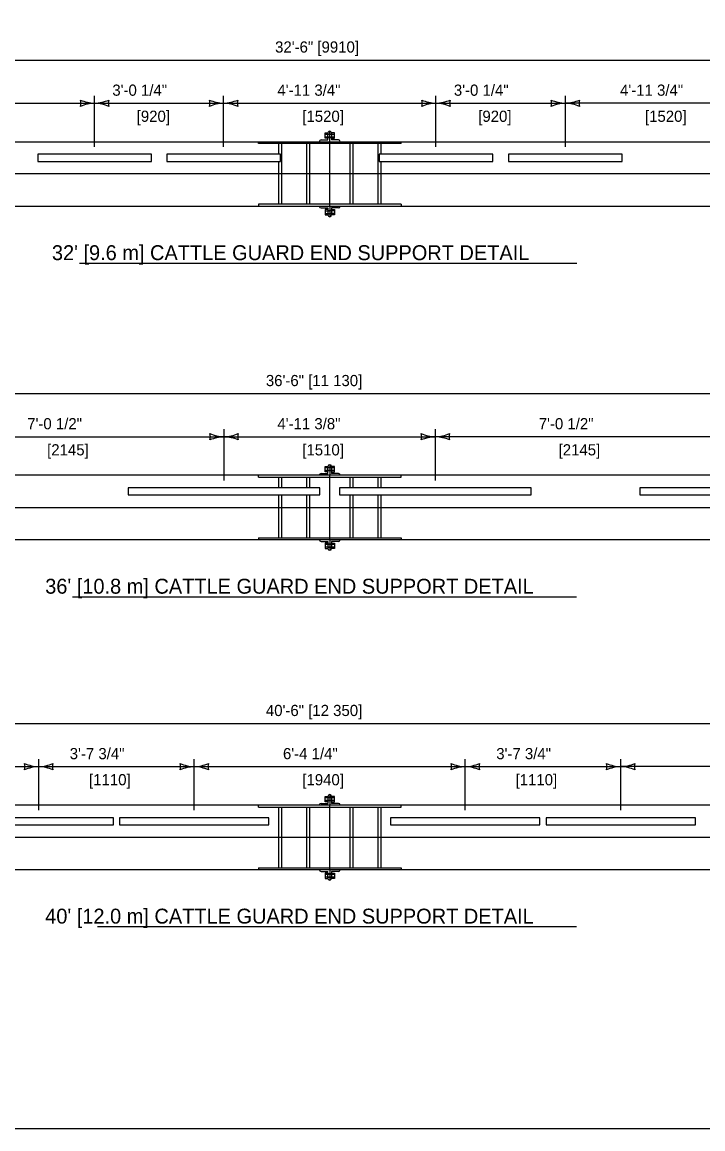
# Model space of a CAD drawing. Extents: x 49991.4 to 50021, y 49987.6 to 50011.4.
# Drawn here: x 50003.05 to 50006.69, y 49987.8 to 49993.74 of the extents above; entities that cross this region are included whole.
import ezdxf

# ---------------------------------------------------------------- set-up
doc = ezdxf.new("R2010")
doc.units = 0
for name, color, linetype in [('Level 1', 7, 'Continuous'), ('Level 2', 7, 'Continuous'), ('Level 3', 7, 'Continuous'), ('Level 4', 7, 'Continuous'), ('Level 5', 7, 'Continuous')]:
    doc.layers.add(name, color=color, linetype=linetype)

msp = doc.modelspace()

# ---------------------------------------------------------------- linework, layer by layer
at = {"layer": 'Level 1'}
for p, q in [((50004.669, 49993.1125), (50004.669, 49993.141)), ((50004.669, 49993.141), (50004.684, 49993.141)), ((50004.669, 49993.1339), (50004.7185, 49993.1339)), ((50004.684, 49993.1035), (50004.684, 49993.141)), ((50004.6937, 49993.0937), (50004.6937, 49993.1508)), ((50004.7185, 49993.141), (50004.7035, 49993.141)), ((50004.7035, 49993.141), (50004.7035, 49993.1035)), ((50004.7185, 49993.1125), (50004.7185, 49993.141)), ((50000.9788, 49993.0937), (50008.4087, 49993.0937)), ((50004.3112, 49993.084), (50004.3112, 49993.0937)), ((50005.0762, 49993.084), (50004.3112, 49993.084)), ((50004.4195, 49993.084), (50004.4195, 49993.0265)), ((50004.4355, 49993.084), (50004.4355, 49992.7585)), ((50004.5695, 49993.084), (50004.5695, 49992.7585)), ((50004.5855, 49993.084), (50004.5855, 49992.7585)), ((50004.6472, 49993.1035), (50004.684, 49993.1035)), ((50004.669, 49993.1196), (50004.7185, 49993.1196)), ((50004.684, 49993.1125), (50004.669, 49993.1125)), ((50004.6937, 49992.7487), (50004.6937, 49993.0937)), ((50004.7035, 49993.1125), (50004.7185, 49993.1125)), ((50004.7402, 49993.1035), (50004.7035, 49993.1035)), ((50004.802, 49993.084), (50004.802, 49992.7585)), ((50004.818, 49993.084), (50004.818, 49992.7585)), ((50004.952, 49993.084), (50004.952, 49992.7585)), ((50004.968, 49993.084), (50004.968, 49993.0265)), ((50005.0762, 49993.084), (50005.0762, 49993.0937)), ((50003.7383, 49993.0265), (50003.1287, 49993.0265)), ((50003.1287, 49993.0265), (50003.1287, 49992.9884)), ((50003.7383, 49992.9884), (50003.7383, 49993.0265)), ((50004.4295, 49993.0265), (50003.8199, 49993.0265)), ((50003.8199, 49993.0265), (50003.8199, 49992.9884)), ((50004.4295, 49992.9884), (50004.4295, 49993.0265)), ((50005.5676, 49993.0265), (50004.958, 49993.0265)), ((50004.958, 49993.0265), (50004.958, 49992.9884)), ((50005.5676, 49992.9884), (50005.5676, 49993.0265)), ((50006.2614, 49993.0265), (50005.6518, 49993.0265)), ((50005.6518, 49993.0265), (50005.6518, 49992.9884)), ((50006.2614, 49992.9884), (50006.2614, 49993.0265)), ((50003.1287, 49992.9884), (50003.7383, 49992.9884)), ((50003.8199, 49992.9884), (50004.4295, 49992.9884)), ((50004.4195, 49992.9884), (50004.4195, 49992.7585)), ((50004.958, 49992.9884), (50005.5676, 49992.9884)), ((50004.968, 49992.9884), (50004.968, 49992.7585)), ((50005.6518, 49992.9884), (50006.2614, 49992.9884)), ((50008.4087, 49992.9212), (50000.9788, 49992.9212)), ((50004.6937, 49992.9212), (50004.4079, 49992.9212)), ((50000.9788, 49992.7487), (50008.4087, 49992.7487)), ((50005.0762, 49992.7585), (50004.3112, 49992.7585)), ((50004.3112, 49992.7585), (50004.3112, 49992.7487)), ((50004.6472, 49992.739), (50004.684, 49992.739)), ((50004.684, 49992.73), (50004.669, 49992.73)), ((50004.669, 49992.73), (50004.669, 49992.7015)), ((50004.669, 49992.7229), (50004.6937, 49992.7229)), ((50004.684, 49992.739), (50004.684, 49992.7015)), ((50004.6937, 49992.7487), (50004.6937, 49992.6919)), ((50004.7185, 49992.7229), (50004.6937, 49992.7229)), ((50004.7402, 49992.739), (50004.7035, 49992.739)), ((50004.7035, 49992.739), (50004.7035, 49992.7015)), ((50004.7035, 49992.73), (50004.7185, 49992.73)), ((50004.7185, 49992.73), (50004.7185, 49992.7015)), ((50005.0762, 49992.7585), (50005.0762, 49992.7487)), ((50004.669, 49992.7086), (50004.6937, 49992.7086)), ((50004.669, 49992.7015), (50004.684, 49992.7015)), ((50004.7185, 49992.7086), (50004.6937, 49992.7086)), ((50004.7185, 49992.7015), (50004.7035, 49992.7015)), ((50004.6937, 49991.3614), (50004.6937, 49991.3045)), ((50008.8676, 49991.3045), (50000.5199, 49991.3045)), ((50004.3112, 49991.2947), (50004.3112, 49991.3045)), ((50004.3112, 49991.2947), (50005.0762, 49991.2947)), ((50004.4195, 49991.2947), (50004.4195, 49991.2373)), ((50004.4355, 49991.2947), (50004.4355, 49991.2373)), ((50004.5695, 49991.2947), (50004.5695, 49991.2373)), ((50004.5855, 49991.2947), (50004.5855, 49991.2373)), ((50004.6472, 49991.3142), (50004.684, 49991.3142)), ((50004.669, 49991.3232), (50004.669, 49991.3517)), ((50004.669, 49991.3517), (50004.684, 49991.3517)), ((50004.7185, 49991.3446), (50004.669, 49991.3446)), ((50004.7185, 49991.3303), (50004.669, 49991.3303)), ((50004.684, 49991.3232), (50004.669, 49991.3232)), ((50004.684, 49991.3142), (50004.684, 49991.3517)), ((50004.6937, 49990.9594), (50004.6937, 49991.3045)), ((50004.7185, 49991.3517), (50004.7035, 49991.3517)), ((50004.7035, 49991.3517), (50004.7035, 49991.3142)), ((50004.7035, 49991.3232), (50004.7185, 49991.3232)), ((50004.7402, 49991.3142), (50004.7035, 49991.3142)), ((50004.7185, 49991.3232), (50004.7185, 49991.3517)), ((50004.802, 49991.2947), (50004.802, 49991.2373)), ((50004.818, 49991.2947), (50004.818, 49991.2373)), ((50004.952, 49991.2947), (50004.952, 49991.2373)), ((50004.968, 49991.2947), (50004.968, 49991.2373)), ((50005.0762, 49991.2947), (50005.0762, 49991.3045)), ((50004.6412, 49991.2373), (50003.6137, 49991.2373)), ((50003.6137, 49991.2373), (50003.6137, 49991.1991)), ((50004.6412, 49991.1991), (50004.6412, 49991.2373)), ((50005.7738, 49991.2373), (50004.7462, 49991.2373)), ((50004.7462, 49991.2373), (50004.7462, 49991.1991)), ((50005.7738, 49991.1991), (50005.7738, 49991.2373)), ((50007.3825, 49991.2373), (50006.355, 49991.2373)), ((50006.355, 49991.2373), (50006.355, 49991.1991)), ((50003.6137, 49991.1991), (50004.6412, 49991.1991)), ((50004.4195, 49991.1991), (50004.4195, 49990.9692)), ((50004.4355, 49991.1991), (50004.4355, 49990.9692)), ((50004.5695, 49991.1991), (50004.5695, 49990.9692)), ((50004.5855, 49991.1991), (50004.5855, 49990.9692)), ((50004.7462, 49991.1991), (50005.7738, 49991.1991)), ((50004.802, 49991.1991), (50004.802, 49990.9692)), ((50004.818, 49991.1991), (50004.818, 49990.9692)), ((50004.952, 49991.1991), (50004.952, 49990.9692)), ((50004.968, 49991.1991), (50004.968, 49990.9692)), ((50006.355, 49991.1991), (50007.3825, 49991.1991)), ((50000.5199, 49991.132), (50008.8676, 49991.132)), ((50000.5199, 49990.9594), (50008.8676, 49990.9594)), ((50004.3112, 49990.9692), (50005.0762, 49990.9692)), ((50004.3112, 49990.9692), (50004.3112, 49990.9594)), ((50004.6472, 49990.9497), (50004.684, 49990.9497)), ((50004.684, 49990.9407), (50004.669, 49990.9407)), ((50004.669, 49990.9407), (50004.669, 49990.9122)), ((50004.684, 49990.9497), (50004.684, 49990.9122)), ((50004.6937, 49990.9594), (50004.6937, 49990.9025)), ((50004.7402, 49990.9497), (50004.7035, 49990.9497)), ((50004.7035, 49990.9497), (50004.7035, 49990.9122)), ((50004.7035, 49990.9407), (50004.7185, 49990.9407)), ((50004.7185, 49990.9407), (50004.7185, 49990.9122)), ((50005.0762, 49990.9692), (50005.0762, 49990.9594)), ((50004.7185, 49990.9336), (50004.669, 49990.9336)), ((50004.7185, 49990.9193), (50004.669, 49990.9193)), ((50004.669, 49990.9122), (50004.684, 49990.9122)), ((50004.7185, 49990.9122), (50004.7035, 49990.9122)), ((50004.669, 49989.5536), (50004.669, 49989.5821)), ((50004.669, 49989.5821), (50004.684, 49989.5821)), ((50004.7185, 49989.575), (50004.669, 49989.575)), ((50004.684, 49989.5821), (50004.684, 49989.5446)), ((50004.6937, 49989.5918), (50004.6937, 49989.5348)), ((50004.7185, 49989.5821), (50004.7035, 49989.5821)), ((50004.7035, 49989.5821), (50004.7035, 49989.5446)), ((50004.7185, 49989.5536), (50004.7185, 49989.5821)), ((50009.3231, 49989.5348), (50000.0644, 49989.5348)), ((50004.3112, 49989.5251), (50004.3112, 49989.5348)), ((50004.3112, 49989.5251), (50005.0762, 49989.5251)), ((50004.4195, 49989.5251), (50004.4195, 49989.1996)), ((50004.4355, 49989.5251), (50004.4355, 49989.1996)), ((50004.5695, 49989.5251), (50004.5695, 49989.1996)), ((50004.5855, 49989.5251), (50004.5855, 49989.1996)), ((50004.6472, 49989.5446), (50004.684, 49989.5446)), ((50004.7185, 49989.5607), (50004.669, 49989.5607)), ((50004.684, 49989.5536), (50004.669, 49989.5536)), ((50004.6937, 49989.1898), (50004.6937, 49989.5348)), ((50004.7035, 49989.5536), (50004.7185, 49989.5536)), ((50004.7402, 49989.5446), (50004.7035, 49989.5446)), ((50004.802, 49989.5251), (50004.802, 49989.1996)), ((50004.818, 49989.5251), (50004.818, 49989.1996)), ((50004.952, 49989.5251), (50004.952, 49989.1996)), ((50004.968, 49989.5251), (50004.968, 49989.1996)), ((50005.0762, 49989.5251), (50005.0762, 49989.5348)), ((50003.5341, 49989.4677), (50002.734, 49989.4677)), ((50003.5341, 49989.4295), (50003.5341, 49989.4677)), ((50004.3675, 49989.4676), (50003.5674, 49989.4676)), ((50003.5674, 49989.4676), (50003.5674, 49989.4294)), ((50004.3675, 49989.4294), (50004.3675, 49989.4676)), ((50005.82, 49989.4676), (50005.0199, 49989.4676)), ((50005.0199, 49989.4676), (50005.0199, 49989.4294)), ((50005.82, 49989.4294), (50005.82, 49989.4676)), ((50006.6535, 49989.4677), (50005.8533, 49989.4677)), ((50005.8533, 49989.4677), (50005.8533, 49989.4295)), ((50006.6535, 49989.4295), (50006.6535, 49989.4677)), ((50002.734, 49989.4295), (50003.5341, 49989.4295)), ((50003.5674, 49989.4294), (50004.3675, 49989.4294)), ((50005.0199, 49989.4294), (50005.82, 49989.4294)), ((50005.8533, 49989.4295), (50006.6535, 49989.4295)), ((50009.3231, 49989.3623), (50000.0644, 49989.3623)), ((50000.0644, 49989.1898), (50009.3231, 49989.1898)), ((50004.3112, 49989.1996), (50005.0762, 49989.1996)), ((50004.3112, 49989.1996), (50004.3112, 49989.1898)), ((50004.6472, 49989.1801), (50004.684, 49989.1801)), ((50004.684, 49989.1711), (50004.669, 49989.1711)), ((50004.669, 49989.1711), (50004.669, 49989.1426)), ((50004.7185, 49989.164), (50004.669, 49989.164)), ((50004.684, 49989.1426), (50004.684, 49989.1801)), ((50004.6937, 49989.1898), (50004.6937, 49989.1328)), ((50004.7402, 49989.1801), (50004.7035, 49989.1801)), ((50004.7035, 49989.1801), (50004.7035, 49989.1426)), ((50004.7035, 49989.1711), (50004.7185, 49989.1711)), ((50004.7185, 49989.1711), (50004.7185, 49989.1426)), ((50005.0762, 49989.1996), (50005.0762, 49989.1898)), ((50004.7185, 49989.1497), (50004.669, 49989.1497)), ((50004.669, 49989.1426), (50004.684, 49989.1426)), ((50004.7185, 49989.1426), (50004.7035, 49989.1426))]:
    msp.add_line(p, q, dxfattribs=at)
msp.add_lwpolyline([(49999.3835, 49998.9992), (50016.7501, 49998.9992), (50016.7501, 49987.7988), (49999.3835, 49987.7988)], close=True, dxfattribs=at)
for centre, start, end in [((50004.6937, 49993.141), 359.92784, 180.07216), ((50004.6472, 49993.0937), 90, 180), ((50004.7402, 49993.0937), 0, 90), ((50004.6472, 49992.7487), 180, 270), ((50004.7402, 49992.7487), 270, 0), ((50004.6937, 49992.7016), 180.89562, 359.10438), ((50004.6937, 49991.3517), 0.05538, 179.94462), ((50004.6472, 49991.3045), 90, 180), ((50004.7402, 49991.3045), 0, 90), ((50004.6472, 49990.9594), 180, 270), ((50004.7402, 49990.9594), 270, 0), ((50004.6937, 49990.9122), 180.29536, 359.70464), ((50004.6937, 49989.5821), 0.02089, 179.97911), ((50004.6472, 49989.5348), 90, 180), ((50004.7402, 49989.5348), 0, 90), ((50004.6472, 49989.1898), 180, 270), ((50004.7402, 49989.1898), 270, 0), ((50004.6937, 49989.1426), 179.98487, 0.01513)]:
    msp.add_arc(centre, 0.00975, start, end, dxfattribs=at)
at = {"layer": 'Level 2'}
for p, q in [((50003.3522, 49992.4428), (50006.0174, 49992.4428)), ((50003.3153, 49990.6536), (50006.016, 49990.6536)), ((50003.4488, 49988.8839), (50006.0156, 49988.8839))]:
    msp.add_line(p, q, dxfattribs=at)
at = {"layer": 'Level 3'}
for p, q in [((50002.449, 49993.5322), (50008.4087, 49993.5322)), ((50002.4984, 49993.3006), (50003.4335, 49993.3006)), ((50003.4335, 49993.3006), (50004.1247, 49993.3006)), ((50004.1247, 49993.3006), (50005.2628, 49993.3006)), ((50005.2628, 49993.3006), (50005.9566, 49993.3006)), ((50007.1038, 49993.3006), (50005.9566, 49993.3006)), ((50001.6137, 49991.7429), (50008.8676, 49991.7429)), ((50002.5187, 49991.5114), (50004.1275, 49991.5114)), ((50004.1275, 49991.5114), (50005.26, 49991.5114)), ((50006.8688, 49991.5114), (50005.26, 49991.5114)), ((50000.9974, 49989.9733), (50009.3231, 49989.9733)), ((50001.6812, 49989.7417), (50003.1341, 49989.7417)), ((50003.1341, 49989.7417), (50003.9675, 49989.7417)), ((50003.9675, 49989.7417), (50005.42, 49989.7417)), ((50005.42, 49989.7417), (50006.2534, 49989.7417)), ((50007.7062, 49989.7417), (50006.2534, 49989.7417))]:
    msp.add_line(p, q, dxfattribs=at)
for centre, radius, start, end in [((50003.4427, 49993.5227), 0.2223, 247.45601, 267.63952), ((50003.3053, 49993.3006), 0.0548, 342.13882, 17.86118), ((50003.422, 49993.5333), 0.233, 272.82731, 292.07716), ((50003.5617, 49993.3006), 0.0548, 162.13882, 197.86118), ((50004.1338, 49993.5227), 0.2223, 247.45601, 267.63952), ((50003.9964, 49993.3006), 0.0548, 342.13882, 17.86118), ((50004.1132, 49993.5333), 0.233, 272.82731, 292.07716), ((50004.2529, 49993.3006), 0.0548, 162.13882, 197.86118), ((50005.272, 49993.5227), 0.2223, 247.45601, 267.63952), ((50005.1346, 49993.3006), 0.0548, 342.13882, 17.86118), ((50005.2513, 49993.5333), 0.233, 272.82731, 292.07716), ((50005.391, 49993.3006), 0.0548, 162.13882, 197.86118), ((50005.9657, 49993.5227), 0.2223, 247.45601, 267.63952), ((50005.8283, 49993.3006), 0.0548, 342.13882, 17.86118), ((50005.9451, 49993.5333), 0.233, 272.82731, 292.07716), ((50006.0848, 49993.3006), 0.0548, 162.13882, 197.86118), ((50003.445, 49993.0679), 0.233, 92.82731, 112.07716), ((50003.4244, 49993.0784), 0.2223, 67.45601, 87.63952), ((50004.1361, 49993.0679), 0.233, 92.82731, 112.07716), ((50004.1155, 49993.0784), 0.2223, 67.45601, 87.63952), ((50005.2743, 49993.0679), 0.233, 92.82731, 112.07716), ((50005.2536, 49993.0784), 0.2223, 67.45601, 87.63952), ((50005.9681, 49993.0679), 0.233, 92.82731, 112.07716), ((50005.9474, 49993.0784), 0.2223, 67.45601, 87.63952), ((50004.1366, 49991.7335), 0.2223, 247.45601, 267.63952), ((50003.9992, 49991.5114), 0.0548, 342.13882, 17.86118), ((50004.139, 49991.2786), 0.233, 92.82731, 112.07716), ((50004.116, 49991.7441), 0.233, 272.82731, 292.07716), ((50004.1183, 49991.2892), 0.2223, 67.45601, 87.63952), ((50004.2557, 49991.5114), 0.0548, 162.13882, 197.86118), ((50005.2691, 49991.7335), 0.2223, 247.45601, 267.63952), ((50005.1318, 49991.5114), 0.0548, 342.13882, 17.86118), ((50005.2715, 49991.2786), 0.233, 92.82731, 112.07716), ((50005.2485, 49991.7441), 0.233, 272.82731, 292.07716), ((50005.2508, 49991.2892), 0.2223, 67.45601, 87.63952), ((50005.3882, 49991.5114), 0.0548, 162.13882, 197.86118), ((50003.1432, 49989.9639), 0.2223, 247.45601, 267.63952), ((50003.0058, 49989.7417), 0.0548, 342.13882, 17.86118), ((50003.1226, 49989.9744), 0.233, 272.82212, 292.07197), ((50003.2623, 49989.7417), 0.0548, 162.13363, 197.85599), ((50003.9767, 49989.9638), 0.2223, 247.45082, 267.63433), ((50003.8393, 49989.7417), 0.0548, 342.13363, 17.85599), ((50003.956, 49989.9744), 0.233, 272.82731, 292.07716), ((50004.0957, 49989.7417), 0.0548, 162.13882, 197.86118), ((50005.4291, 49989.9638), 0.2223, 247.45601, 267.63952), ((50005.2918, 49989.7417), 0.0548, 342.13882, 17.86118), ((50005.4085, 49989.9744), 0.233, 272.8325, 292.08235), ((50005.5482, 49989.7417), 0.0548, 162.14401, 197.86637), ((50006.2625, 49989.9639), 0.2223, 247.4612, 267.64471), ((50006.1252, 49989.7417), 0.0548, 342.14401, 17.86637), ((50006.2419, 49989.9744), 0.233, 272.82731, 292.07716), ((50006.3816, 49989.7417), 0.0548, 162.13882, 197.86118), ((50003.1456, 49989.509), 0.233, 92.82731, 112.07716), ((50003.1249, 49989.5196), 0.2223, 67.45082, 87.63433), ((50003.979, 49989.5089), 0.233, 92.82212, 112.07197), ((50003.9583, 49989.5195), 0.2223, 67.45601, 87.63952), ((50005.4315, 49989.5089), 0.233, 92.82731, 112.07716), ((50005.4108, 49989.5195), 0.2223, 67.4612, 87.64471), ((50006.2649, 49989.509), 0.233, 92.8325, 112.08235), ((50006.2442, 49989.5196), 0.2223, 67.45601, 87.63952)]:
    msp.add_arc(centre, radius, start, end, dxfattribs=at)
at = {"layer": 'Level 4'}
for p, q in [((50004.684, 49993.1361), (50004.7035, 49993.1361)), ((50004.684, 49993.1174), (50004.7185, 49993.1174)), ((50004.684, 49992.7251), (50004.6937, 49992.7251)), ((50004.7035, 49992.7251), (50004.6937, 49992.7251)), ((50004.684, 49992.7064), (50004.6937, 49992.7064)), ((50004.7035, 49992.7064), (50004.6937, 49992.7064)), ((50004.7035, 49991.3468), (50004.684, 49991.3468)), ((50004.7035, 49991.3281), (50004.684, 49991.3281)), ((50004.7035, 49990.9358), (50004.684, 49990.9358)), ((50004.7035, 49990.9171), (50004.684, 49990.9171)), ((50004.7035, 49989.5772), (50004.684, 49989.5772)), ((50004.7035, 49989.5585), (50004.684, 49989.5585)), ((50004.7035, 49989.1662), (50004.684, 49989.1662)), ((50004.7035, 49989.1475), (50004.684, 49989.1475))]:
    msp.add_line(p, q, dxfattribs=at)
at = {"layer": 'Level 5'}
for p, q in [((50003.4335, 49993.0665), (50003.4335, 49993.3406)), ((50004.1247, 49993.0665), (50004.1247, 49993.3406)), ((50005.2628, 49993.0665), (50005.2628, 49993.3406)), ((50005.9566, 49993.0665), (50005.9566, 49993.3406)), ((50004.1275, 49991.2773), (50004.1275, 49991.5514)), ((50005.26, 49991.2773), (50005.26, 49991.5514)), ((50005.26, 49991.2773), (50005.26, 49991.5514)), ((50003.1341, 49989.5077), (50003.1341, 49989.7817)), ((50003.9675, 49989.5076), (50003.9675, 49989.7817)), ((50005.42, 49989.5076), (50005.42, 49989.7817)), ((50006.2534, 49989.5077), (50006.2534, 49989.7817))]:
    msp.add_line(p, q, dxfattribs=at)

# ---------------------------------------------------------------- texts
at = {"layer": 'Level 2'}
for s, height, p in [('32\'-6" [9910]', 0.06, (50004.4008, 49993.5722)), ('3\'-0 1/4"', 0.06, (50003.5285, 49993.3406)), ('4\'-11 3/4"', 0.06, (50004.4131, 49993.3406)), ('3\'-0 1/4"', 0.06, (50005.359, 49993.3406)), ('4\'-11 3/4"', 0.06, (50006.2496, 49993.3406)), ('[920]', 0.06, (50003.659, 49993.2006)), ('[1520]', 0.06, (50004.5467, 49993.2006)), ('[920]', 0.06, (50005.4896, 49993.2006)), ('[1520]', 0.06, (50006.3832, 49993.2006)), ("32' [9.6 m] CATTLE GUARD END SUPPORT DETAIL", 0.08, (50003.2047, 49992.4588)), ('36\'-6" [11 130]', 0.06, (50004.3514, 49991.7829)), ('7\'-0 1/2"', 0.06, (50003.0724, 49991.5514)), ('4\'-11 3/8"', 0.06, (50004.4131, 49991.5514)), ('7\'-0 1/2"', 0.06, (50005.8138, 49991.5514)), ('[2145]', 0.06, (50003.179, 49991.4114)), ('[1510]', 0.06, (50004.5467, 49991.4114)), ('[2145]', 0.06, (50005.9203, 49991.4114)), ("36' [10.8 m] CATTLE GUARD END SUPPORT DETAIL", 0.08, (50003.1688, 49990.6696)), ('40\'-6" [12 350]', 0.06, (50004.3515, 49990.0133)), ('3\'-7 3/4"', 0.06, (50003.3001, 49989.7817)), ('6\'-4 1/4"', 0.06, (50004.4431, 49989.7817)), ('3\'-7 3/4"', 0.06, (50005.5861, 49989.7817)), ('[1110]', 0.06, (50003.4037, 49989.6417)), ('[1940]', 0.06, (50004.5467, 49989.6417)), ('[1110]', 0.06, (50005.6896, 49989.6417)), ("40' [12.0 m] CATTLE GUARD END SUPPORT DETAIL", 0.08, (50003.1688, 49988.8999))]:
    msp.add_text(s, height=height, dxfattribs=at).set_placement(p)

doc.saveas('drawing.dxf')
